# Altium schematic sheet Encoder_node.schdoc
size 594 x 419 mm; Symbol: Sheet-Symbol_A2; Company: 嘉立创EDA; Version: V1.0; Page Size: A2; @Project Name: CC_ESP32main; @Page Count: 1; @Update Date: 2026-03-14; @Create Date: 2026-03-14; @Schematic Name: Schematic1; @Page No: 1; @Page Name: P1; Device: Sheet-Symbol_A2; Border: 1; Title Block Position: 3; Width: 2338; Height: 1652; Region Start: 1; X Region Count: 6; Y Region Count: 4; Blade Width: 10; @Board Name: Board1; @Update Time: 19:06:50; @Create Time: 16:49:24
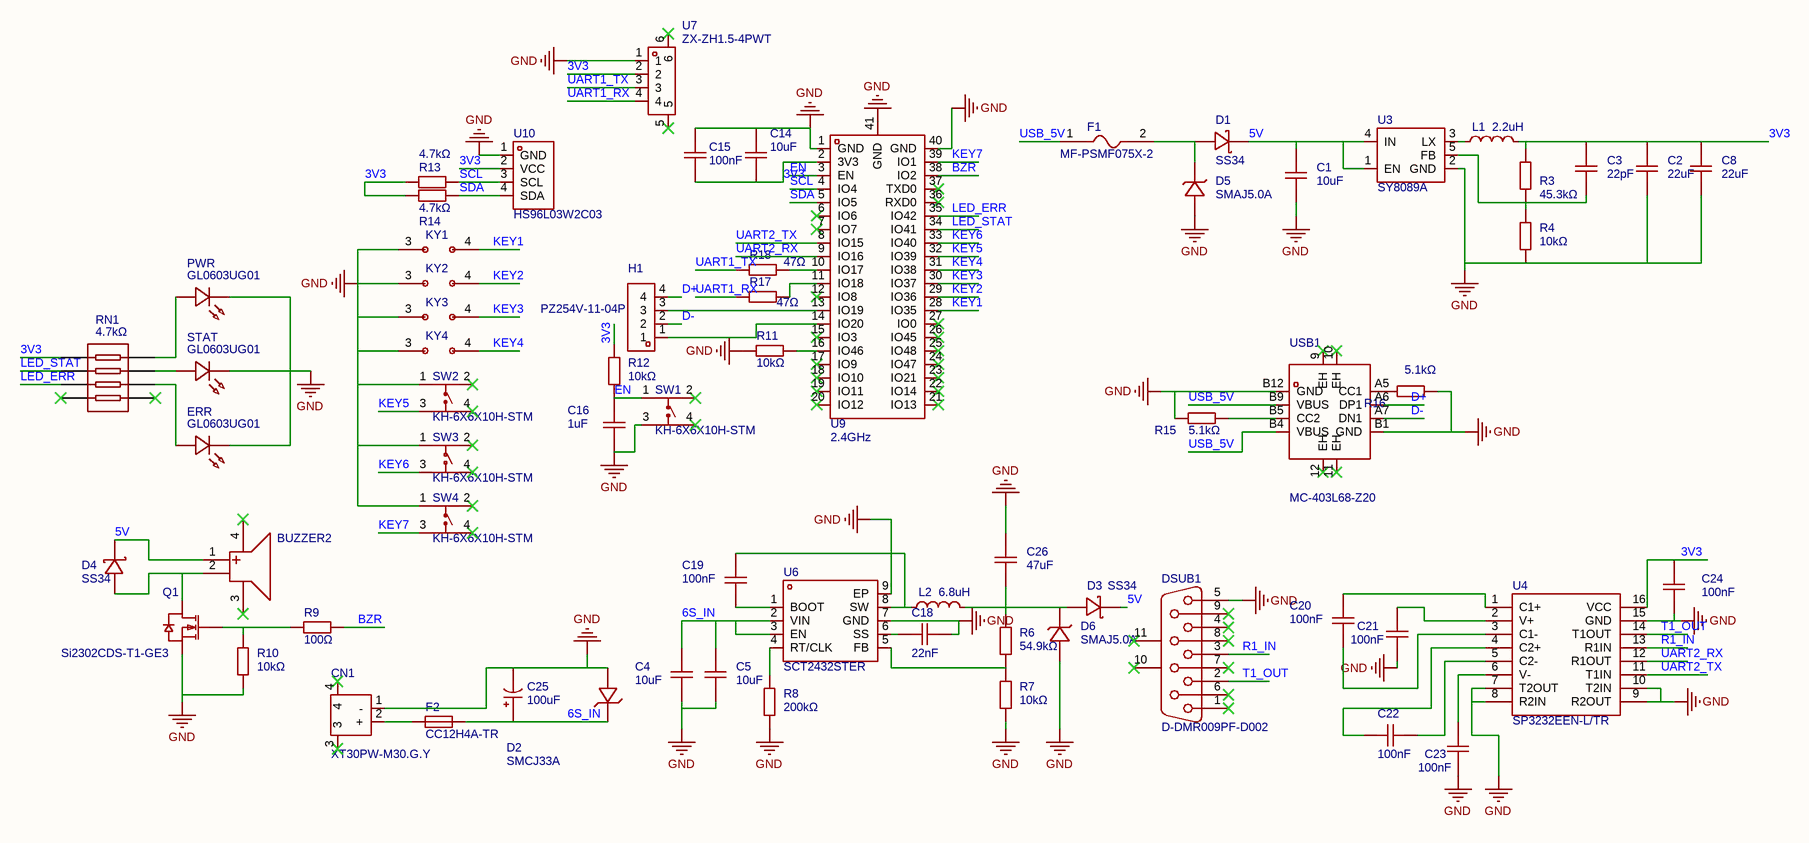
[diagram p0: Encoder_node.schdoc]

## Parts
BUZZER2  2.7kHz  [BUZ-SMD_GSC85XX]  (value not drawn)
C1  10uF  [C0603]
C2  22uF  [C0603]
C3  22pF  [C0603]
C4  10uF  [C1206]
C5  10uF  [C1206]
C8  22uF  [C0603]
C14  10uF  [C0603]
C15  100nF  [C0603]
C16  1uF  [C0603]
C18  22nF  [C0603]
C19  100nF  [C0603]
C20  100nF  [C0603]
C21  100nF  [C0603]
C22  100nF  [C0603]
C23  100nF  [C0603]
C24  100nF  [C0603]
C25  100uF  [CAP-SMD_BD6.3-L6.6-W6.6-LS7.3-FD-H7.7]
C26  47uF  [C1206]
CN1  XT30PW-M30.G.Y  [CONN-TH_XT30PW-M]
D1  SS34  [SMA_L4.3-W2.6-LS5.2-RD]
D2  SMCJ33A  [SMC_L6.9-W5.9-LS7.9-RD]
D3  SS34  [SMA_L4.3-W2.6-LS5.2-RD]
D4  SS34  [SMA_L4.3-W2.6-LS5.2-RD]
D5  SMAJ5.0A  [SMA_L4.3-W2.6-LS5.0-RD]
D6  SMAJ5.0A  [SMA_L4.3-W2.6-LS5.0-RD]
DSUB1  D-DMR009PF-D002  [DSUB-TH_DMR-9S]
ERR  GL0603UG01  [LED0603-RD]
F1  MF-PSMF075X-2  [F0805]
F2  CC12H4A-TR  [F1206]
H1  PZ254V-11-04P  [HDR-TH_4P-P2.54-V-M]
KY1  (no value)  [封装_凯华热插拔-5脚]
KY2  (no value)  [封装_凯华热插拔-5脚]
KY3  (no value)  [封装_凯华热插拔-5脚]
KY4  (no value)  [封装_凯华热插拔-5脚]
L1  2.2uH  [IND-SMD_L4.6-W4.1_MHCI04015]
L2  6.8uH  [IND-SMD_L7.5-W6.6_SRG0650]
PWR  GL0603UG01  [LED0603-RD]
Q1  Si2302CDS-T1-GE3  [SOT-23_L2.9-W1.3-P1.90-LS2.4-BR]
R3  45.3kΩ  [R0603]
R4  10kΩ  [R0603]
R6  54.9kΩ  [R0603]
R7  10kΩ  [R0603]
R8  200kΩ  [R0603]
R9  100Ω  [R0603]
R10  10kΩ  [R0603]
R11  10kΩ  [R0603]
R12  10kΩ  [R0603]
R13  4.7kΩ  [R0603]
R14  4.7kΩ  [R0603]
R15  5.1kΩ  [R0603]
R16  5.1kΩ  [R0603]
R17  47Ω  [R0603]
R18  47Ω  [R0603]
RN1  4.7kΩ  [RES-ARRAY-SMD_0603-8P-L3.2-W1.6-BL]
STAT  GL0603UG01  [LED0603-RD]
SW1  KH-6X6X10H-STM  [SW-SMD_4P-L6.0-W6.0-P4.50-LS9.0-H10.0]
SW2  KH-6X6X10H-STM  [SW-SMD_4P-L6.0-W6.0-P4.50-LS9.0-H10.0]
SW3  KH-6X6X10H-STM  [SW-SMD_4P-L6.0-W6.0-P4.50-LS9.0-H10.0]
SW4  KH-6X6X10H-STM  [SW-SMD_4P-L6.0-W6.0-P4.50-LS9.0-H10.0]
U3  SY8089A  [SOT-23-5_L3.0-W1.7-P0.95-LS2.8-BL]
U4  SP3232EEN-L/TR  [SOIC-16_L9.9-W3.9-P1.27-LS6.0-BL]
U6  SCT2432STER  [ESOP-8_L4.9-W3.9-P1.27-LS6.0-BL-EP]
U7  ZX-ZH1.5-4PWT  [CONN-SMD_4P-P1.50_ZX-ZH1.5-4PWT]
U9  2.4GHz  [WIFIM-SMD_ESP32-S3-WROOM-1-N8]
U10  HS96L03W2C03  [OLED-TH_L27.8-W27.2-P2.54_C9900033791]
USB1  MC-403L68-Z20  [USB-C-SMD_MC-403L68-Z20]

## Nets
GND: C1.1 C2.1 C4.2 C5.2 C8.1 C14.2 C15.2 C16.1 C18.1 C21.2 C23.1 C24.1 C25.2 C26.1 CN1.1(-) D2.2(A) D5.2(A) D6.2(A) DSUB1.5 ERR.1(K) KY1.3 KY2.3 KY3.3 KY4.3 PWR.1(K) Q1.2(S) R4.1 R7.1 R8.1 R10.2 R11.1 R15.1 R16.2 STAT.1(K) SW1.3(C) SW2.1(A) SW3.1(A) SW4.1(A) U3.2(GND) U4.7(T2OUT) U4.8(R2IN) U4.9(R2OUT) U4.10(T2IN) U4.15(GND) U6.7(GND) U6.9(EP) U7.1 U9.1(GND) U9.40(GND) U9.41(GND) U10.1(GND) USB1.B1(GND) USB1.B12(GND)
3V3: C2.2 C3.2 C8.2 C14.1 C15.1 C24.2 L1.2 R3.2 R12.2 R13.1 R14.2 RN1.1 U4.16(VCC) U7.2 U9.2(3V3) U10.2(VCC)
5V: BUZZER2.1(+) C1.2 D1.1(K) D3.1(K) D4.1(K) U3.1(EN) U3.4(IN)
6S_IN: C4.1 C5.1 C25.1 D2.1(K) F2.2 U6.2(VIN) U6.3(EN)
BZR: R9.1 U9.38(IO2)
D+: H1.4 USB1.A6(DP1)
D-: H1.2 USB1.A7(DN1)
EN: C16.2 R12.1 SW1.1(A) U9.3(EN)
KEY1: KY1.4 U9.28(IO35)
KEY2: KY2.4 U9.29(IO36)
KEY3: KY3.4 U9.30(IO37)
KEY4: KY4.4 U9.31(IO38)
KEY5: SW2.3(C) U9.32(IO39)
KEY6: SW3.3(C) U9.33(IO40)
KEY7: SW4.3(C) U9.39(IO1)
LED_ERR: RN1.3 U9.35(IO42)
LED_STAT: RN1.2 U9.34(IO41)
R1_IN: DSUB1.3 U4.13(R1IN)
SCL: R13.2 U9.4(IO4) U10.3(SCL)
SDA: R14.1 U9.5(IO5) U10.4(SDA)
T1_OUT: DSUB1.2 U4.14(T1OUT)
UART1_RX: R17.1 U7.4
UART1_TX: R18.1 U7.3
UART2_RX: U4.12(R1OUT) U9.9(IO16)
UART2_TX: U4.11(T1IN) U9.8(IO15)
USB_5V: F1.1 USB1.B4(VBUS) USB1.B9(VBUS)
NetBUZZER2_2: BUZZER2.2(-) D4.2(A) Q1.3(D)
NetC3_1: C3.1 R3.1 R4.2 U3.5(FB)
NetC18_2: C18.2 U6.6(SS)
NetC19_1: C19.1 L2.1 U6.8(SW)
NetC19_2: C19.2 U6.1(BOOT)
NetC20_1: C20.1 U4.1(C1+)
NetC20_2: C20.2 U4.3(C1-)
NetC21_1: C21.1 U4.2(V+)
NetC22_1: C22.1 U4.4(C2+)
NetC22_2: C22.2 U4.5(C2-)
NetC23_2: C23.2 U4.6(V-)
NetC26_2: C26.2 D3.2(A) D6.1(K) L2.2 R6.2
NetCN1_2: CN1.2(+) F2.1
NetD1_2: D1.2(A) D5.1(K) F1.2
NetERR_2: ERR.2(A) RN1.6
NetH1_1: H1.1 U9.14(IO20)
NetH1_3: H1.3 U9.13(IO19)
NetL1_1: L1.1 U3.3(LX)
NetPWR_2: PWR.2(A) RN1.8
NetQ1_1: Q1.1(G) R9.2 R10.1
NetR6_1: R6.1 R7.2 U6.5(FB)
NetR8_2: R8.2 U6.4(RT/CLK)
NetR11_2: R11.2 U9.16(IO46)
NetR15_2: R15.2 USB1.B5(CC2)
NetR16_1: R16.1 USB1.A5(CC1)
NetR17_2: R17.2 U9.11(IO18)
NetR18_2: R18.2 U9.10(IO17)
NetRN1_7: RN1.7 STAT.2(A)

Not connected (* = marked no-connect by the designer): BUZZER2 3* 4*; CN1 3* 4*; DSUB1 1* 4* 6* 7* 8* 9* 10(MH1)* 11(MH2)*; RN1 4* 5*; SW1 2(B)* 4(D)*; SW2 2(B)* 4(D)*; SW3 2(B)* 4(D)*; SW4 2(B)* 4(D)*; U7 5* 6*; U9 6(IO6)* 7(IO7)* 12(IO8)* 15(IO3)* 17(IO9)* 18(IO10)* 19(IO11)* 20(IO12)* 21(IO13)* 22(IO14)* 23(IO21)* 24(IO47)* 25(IO48)* 26(IO45)* 27(IO0)* 36(RXD0)* 37(TXD0)*; USB1 9(EH)* 10(EH)* 11(EH)* 12(EH)*

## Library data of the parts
BUZZER2 = GSC8530YA-16R2700: 驱动方式:无源(外部驱动);构造类型:电磁式;频率:2.7kHz;声压(SPL):85dB;; Manufacturer: INGHAi(赢海); AddInBom: yes; ModelId: 336000c5a3324556be9726b4453771b80819f05c4eef4c71ace90d822a990e87; ModelName: BUZ-SMD_4P-L8.5-W8.5-H3.0; ModelTransform: 342.519,342.519,0,270,0,0,0,0,0; Voltage - Supply: 2V~4.5V; Sound Pressure Level(SPL): 85dB
C1-C3 C8 = CGA0603X5R106K100JT: 容值:10uF;精度:±10%;额定电压:10V;温度系数:X5R;; Manufacturer: HRE(芯声); AddInBom: yes; ModelId: ac125912035d415993ca9572d50418b10819f05c4eef4c71ace90d822a990e87; ModelName: C0603_L1.6-W0.8-H0.8; ModelTransform: 62.992,31.496,0,0,0,0,0,0,0; Tolerance: ±10%; Voltage Rating: 10V; Temperature Coefficient: X5R
C4 C5 = HGC1206R5106K500NSPJ: 容值:10uF;精度:±10%;额定电压:50V;温度系数:X5R;; Manufacturer: Chinocera(华瓷); AddInBom: yes; ModelId: e4be705b945545a48e666415e3682bd80819f05c4eef4c71ace90d822a990e87; ModelName: C1206_L3.2-W1.6-H1.3; ModelTransform: 125.984,62.992,0,0,0,0,0,0,0; Tolerance: ±10%; Voltage Rating: 50V; Temperature Coefficient: X5R
C14-C16 C18-C24 = CGA0603X5R106K100JT: 容值:10uF;精度:±10%;额定电压:10V;温度系数:X5R;; Manufacturer: HRE(芯声); 3D Model: ac125912035d415993ca9572d50418b10819f05c4eef4c71ace90d822a990e87; 3D Model Transform: 62.992,31.496,0,0,0,0,0,0,0; Tolerance: ±10%; Voltage Rating: 10V; Temperature Coefficient: X5R; AddInBom: yes; ModelName: C0603_L1.6-W0.8-H0.8
C25 = JVJ50V100M6x8: 容值:100uF;精度:±20%;额定电压:50V;纹波电流:140mA@120Hz;; Manufacturer: JIERR(捷而瑞); AddInBom: yes; ModelId: ccbda52dceed4b139172c40f75c9da3f0819f05c4eef4c71ace90d822a990e87; ModelTransform: 287.401,259.842,0,0,0,0,0,0,0; Tolerance: ±20%; Voltage Rating: 50V; Lifetime: 2000hrs@105℃
C26 = HGC1206R5106K500NSPJ: 容值:10uF;精度:±10%;额定电压:50V;温度系数:X5R;; Manufacturer: Chinocera(华瓷); 3D Model: e4be705b945545a48e666415e3682bd80819f05c4eef4c71ace90d822a990e87; 3D Model Transform: 125.984,62.992,0,0,0,0,0,0,0; Tolerance: ±10%; Voltage Rating: 50V; Temperature Coefficient: X5R; AddInBom: yes; ModelName: C1206_L3.2-W1.6-H1.3
CN1 = XT30PW-M30.G.Y: Socket,DCsupply,XT30,male,PIN:2; Manufacturer: AMASS(艾迈斯); AddInBom: yes; ModelId: 722652c2597f41cd937322584dc4b29b0819f05c4eef4c71ace90d822a990e87; ModelTransform: 523.621,549.2115,0,0,0,0,-0.005,-39.568,-78.74; Rated current: 15A; Rated voltage: 500VDC; Connector type: 航模插头; Wire gauge: 16/18/20AWG; contact resistance: 1.2mΩ; interface form: 公头
D1 D3 = SS34_C8678: 二极管配置:独立式;正向压降(Vf):550mV@3A;直流反向耐压(Vr):40V;整流电流:3A;; Manufacturer: MDD(辰达半导体); AddInBom: yes; ModelId: e3551acb3c5a4975a5e9d36087fe1fa20819f05c4eef4c71ace90d822a990e87; ModelTransform: 185.039,102.362,0,0,0,0,0,0,0; Diode Configuration: 独立式; Voltage - DC Reverse(Vr): 40V; Current - Rectified: 3A; Reverse Leakage Current (Ir): 500uA@40V; Operating Junction Temperature Range: -55℃~+125℃
D2 = SMCJ33A_C224049: 极性:单向;反向截止电压(Vrwm):33V;钳位电压:53.3V;峰值脉冲电流(Ipp):28.2A@10/1000us;峰值脉冲功率(Ppp):1.5kW@10/1000us;击穿电压:40.6V;; Manufacturer: Littelfuse(美国力特); AddInBom: yes; ModelId: 181deed3e51b4528a83dd624c23bafda0819f05c4eef4c71ace90d822a990e87; ModelTransform: 314.96,236.22,0,0,0,0,0,0,0; Polarity: 单向; Reverse Stand-Off Voltage (Vrwm): 33V; Clamping Voltage: 53.3V; Voltage - Breakdown: 40.6V; Reverse Leakage Current (Ir): 1uA; level of protection: IEC 61000-4-4；IEC 61000-4-2; Type: TVS
D4 = SS34_C8678: 二极管配置:独立式;正向压降(Vf):550mV@3A;直流反向耐压(Vr):40V;整流电流:3A;; Manufacturer: MDD(辰达半导体); 3D Model: e3551acb3c5a4975a5e9d36087fe1fa20819f05c4eef4c71ace90d822a990e87; 3D Model Transform: 185.039,102.362,0,0,0,0,0,0,0; Diode Configuration: 独立式; Voltage - DC Reverse(Vr): 40V; Current - Rectified: 3A; Reverse Leakage Current (Ir): 500uA@40V; Operating Junction Temperature Range: -55℃~+125℃; AddInBom: yes
D5 D6 = SMAJ5.0A_C19077523: 极性:单向;反向截止电压(Vrwm):5V;钳位电压:9.2V;峰值脉冲电流(Ipp):43.5A@10/1000us;峰值脉冲功率(Ppp):400W@10/1000us;击穿电压:7V;; Manufacturer: R+O(宏嘉诚); AddInBom: yes; ModelId: 8d2dd2e50a3a4b27821fa63d469a8f110819f05c4eef4c71ace90d822a990e87; ModelTransform: 196.85,102.362,0,0,0,0,0,0,0; Polarity: 单向; Reverse Stand-Off Voltage (Vrwm): 5V; Clamping Voltage: 9.2V; Voltage - Breakdown: 7V; Reverse Leakage Current (Ir): 800uA; Number of Channels: 单路; level of protection: IEC 61000-4-2; Type: TVS
DSUB1 = D-DMR009PF-D002: 连接器类型:常规D-Sub;公母:母;总PIN位数:9P;安装方式:弯插;排数:2;额定电流-信号脚:3A;工作温度:-45℃~+85℃;; Manufacturer: Ckmtw(灿科盟); Symbol: DMR-9S; AddInBom: yes; ModelId: 45662a01dd4a43f09f16f1e1b95d76320819f05c4eef4c71ace90d822a990e87; ModelTransform: 1216.533,728.34496,0,90,0,0,256.102,0.118,-137.795; Gender: 母; Current Rating-Signal: 3A
ERR PWR STAT = GL0603UG01: Manufacturer: Guiguang light(桂光光电); Add into BOM: yes; 3D Model: 3c2caa1a3e7d4a5a87f46b87d898ef41; 3D Model Transform: v2:[39.37007874015748,0,0,0,39.37007874015748,0,0,0,39.37007874015748,0.001,-0.001,0]
F1 = MF-PSMF075X-2: 耐压(Vmax):6V;最大电流(Imax):-;保持电流(Ihold):-;跳闸电流(Itrip):-;; Manufacturer: BOURNS; AddInBom: yes; ModelId: 57e2aa106f9143e8b6ab832aebb31c780819f05c4eef4c71ace90d822a990e87; ModelName: F0805_L2.1-W1.4-H0.8; ModelTransform: 82.677,55.118,0,0,0,0,0.0005,0,0; Voltage - Max: 6V; Power Dissipation: 600mW; Resistance - Initial (Ri) (Min): 90mΩ; Resistance - Post Trip (R1) (Max): 350mΩ
F2 = CC12H4A-TR: 类型:贴片式保险丝;额定电流:4A;额定电压:63V;分断能力:50A;; Manufacturer: EATON(伊顿); AddInBom: yes; ModelId: f1628daad26847a79b887277a2bc85410819f05c4eef4c71ace90d822a990e87; ModelName: F1206_L3.2-W1.7-H0.6; ModelTransform: 125.984,66.929,0,0,0,0,0,0,0; Type: 贴片式保险丝; Current Rating: 4A; Voltage Rating (DC): 63V; Melting I2t: 3.2; Interrupt Rating: 50A
H1 = PZ254V-11-04P: 插针结构:1x4P;间距:2.54mm;行距:-;圆针/方针:方针;安装方式:直插;排数:单排;总PIN位数:4P;额定电流:3A;额定电压:250V;配合针长度:6mm;塑高:2.5mm;端接针长度:3mm;触头材质:-;工作温度:-40℃~+105℃;颜色:黑色;; Manufacturer: XFCN(兴飞); Symbol: PZ254V-11-04P_C2691448; AddInBom: yes; ModelId: 112f4d05e8d64e99ab9a333894bea4f90819f05c4eef4c71ace90d822a990e87; ModelName: HDR-TH_4P-P2.54-M-LI-1X4P; ModelTransform: 399.999,104.7242,0,0,0,0,0,0,-118.11; Pin Structure: 1x4P; Pitch: 2.54mm; Circluar Pins/Square Pins: 方针; Current Rating: 3A; Voltage Rating (Max): 250V
KY1-KY4 = 凯华热插拔-5脚: AddInBom: yes
L1 = SRG0420-2R2-M: 电感值:2.2uH;精度:±20%;额定电流:4A;饱和电流(Isat):5A;类型:一体成型电感;; Manufacturer: JIERR(捷而瑞); AddInBom: yes; Tolerance: ±20%; Current Rating: 4A; Current - Saturation(Isat): 5A; DC Resistance(DCR): 49mΩ; Type: 一体成型电感
L2 = SRG0650-6R8-M: 电感值:6.8uH;精度:±20%;额定电流:6A;饱和电流(Isat):6.5A;类型:一体成型电感;; Manufacturer: JIERR(捷而瑞); AddInBom: yes; Tolerance: ±20%; Current Rating: 6A; Current - Saturation(Isat): 6.5A; DC Resistance(DCR): 32mΩ; Type: 一体成型电感
Q1 = Si2302CDS-T1-GE3: 类型:1个N沟道;漏源电压(Vdss):20V;连续漏极电流(Id):2.9A;导通电阻(RDS(on)@Vgs,Id):57mΩ@4.5V,3.6A;功率(Pd):550mW;阈值电压(Vgs(th)@Id):850mV@250uA;; Manufacturer: VISHAY(威世); 3D Model: c62791f0466c4ae2a892c056b845b0ca0819f05c4eef4c71ace90d822a990e87; 3D Model Transform: 98.64468,114.173,0,180,0,0,0.001,-0.002,0; Type: 1个N沟道; Drain Source Voltage (Vdss): 20V; Continuous Drain Current (Id): 2.9A; Power Dissipation (Pd): 550mW; Total Gate Charge (Qg@Vgs): 3.5nC@4.5V; Input Capacitance (Ciss@Vds): 320pF@10V; Reverse Transfer Capacitance (Crss@Vds): 5pF@10V; AddInBom: yes; ModelName: SOT-23-3P_L2.9-W1.3-H1.0-LS2.4-P0.95
R3 R4 R6-R8 = 0603WAF5101T5E: 电阻类型:厚膜电阻;阻值:5.1kΩ;精度:±1%;功率:100mW;工作电压:75V;温度系数:±100ppm/℃;; Manufacturer: UNI-ROYAL(厚声); AddInBom: yes; ModelId: fc143cca1e79419f9cd78b61e9279f080819f05c4eef4c71ace90d822a990e87; ModelTransform: 31.8897,63.7794,0,90,0,0,0,0,0; Tolerance: ±1%; Power(Watts): 100mW; Voltage-Supply(Max): 75V
R9-R18 = 0603WAF5101T5E: 电阻类型:厚膜电阻;阻值:5.1kΩ;精度:±1%;功率:100mW;工作电压:75V;温度系数:±100ppm/℃;; Manufacturer: UNI-ROYAL(厚声); 3D Model: fc143cca1e79419f9cd78b61e9279f080819f05c4eef4c71ace90d822a990e87; 3D Model Transform: 31.8897,63.7794,0,90,0,0,0,0,0; Tolerance: ±1%; Power(Watts): 100mW; Voltage-Supply(Max): 75V; AddInBom: yes
RN1 = 4D03WGJ0472T5E: Manufacturer: UNI-ROYAL(厚声); Add into BOM: yes; 3D Model: 551b3dd0a237409fa823f51b33d3f6d1; 3D Model Transform: v2:[39.37007874015748,0,0,0,39.37007874015748,0,0,0,39.37007874015748,0,0,0]; ModelName: R0603-8P_L3.2-W1.6-H0.6
SW1-SW4 = KH-6X6X10H-STM: 电路结构:单刀单掷;按钮形状:圆形按钮;安装方式:立贴;开关长度:6mm;开关宽度:6mm;开关高度:10mm;带支架:不带支架;触点电流:50mA;额定电压:12V;工作寿命:8万次;; Manufacturer: kinghelm(金航标); AddInBom: yes; ModelId: abf5895ced9e4fddb18440718d3315620819f05c4eef4c71ace90d822a990e87; ModelTransform: 354.33,236.25937,0,0,0,0,0,0,0; Circuit: 单刀单掷; Actuator Style: 圆形按钮; Switch Height: 10mm; with Bracket: 不带支架; Contact Current: 50mA; Voltage Rating: 12V; Actuator/Cap Color: 黑色; Life: 8万次
U3 = SY8089A: 功能类型:降压型;工作电压:2.5V~5.5V;输出电压:-;输出电流:2A;输出类型:可调;; Manufacturer: TECH PUBLIC(台舟); AddInBom: yes; ModelId: 0a2a1b8f50944f73965918ad6e5fe1670819f05c4eef4c71ace90d822a990e87; ModelName: SOT-23-5_L2.9-W1.6-H1.1-LS2.8-P0.95; ModelTransform: 118.60433,114.173,0,90,0,0,0.0005,0.0005,0; Function: 降压型; Output Current: 2A; Frequency - Switching: 1MHz; Synchronous Rectifier: 否; Number of Outputs: 1; Topology: 降压式; Quiescent Current: 50uA; Switch tube (built-in/external): 内置; Output Type: 可调
U4 = SP3232EEN-L/TR: 类型:收发器;数据速率:235Kbps;; Manufacturer: MaxLinear(迈凌); AddInBom: yes; ModelId: c21ec766ec2643efb3352f8441994f4e0819f05c4eef4c71ace90d822a990e87; ModelName: SOIC-16_L9.9-W3.9-H1.8-LS6.0-P1.27; ModelTransform: 389.763,236.454,0,0,0,0,0,0,0; Number of Drivers: 2; Voltage - Supply: 3V~5.5V
U6 = SCT2432STER: 功能类型:降压型;输出类型:固定;工作电压:3.8V~40V;输出电压:800mV~40V;输出电流:3.5A;; Manufacturer: SCT(芯洲科技); AddInBom: yes; ModelId: d3e00daa36c445139c055a3b9efb85d20819f05c4eef4c71ace90d822a990e87; ModelName: ESOP-8_L4.9-W3.9-H1.6-LS6.0-P1.27; ModelTransform: 240.157,192.913,0,90,0,0,0,0,0; Function: 降压型; Output Type: 固定; Output Current: 3.5A; Switching Frequency: 300kHz~2.2MHz; Synchronous Rectification: 是; Number of Outputs: 1; Topology: 降压式; Quiescent Current (Iq): 25uA; Switch tube (built-in/external): 内置
U7 = ZX-ZH1.5-4PWT: 插针结构:1x4P;间距:1.5mm;安装方式:卧贴;参考系列:ZH;总PIN数:4P;排数:1;每排PIN数:4;行距:-;额定电流:1A;触头材质:黄铜;触头镀层:锡;工作温度:-25℃~+85℃;; Manufacturer: Megastar(兆星); AddInBom: yes; ModelId: e4d7e67cd57849bbb8ee8d6cc11c6e1d0819f05c4eef4c71ace90d822a990e87; ModelTransform: 354.7237,255.905,0,0,0,0,-0.002,-26.024,0; Pins Structure: 1x4P; Pitch: 1.5mm; Reference Series: ZH; Number of PINs Per Row: 4; Current Rating: 1A; Voltage Rating: 250V; Plastic Material: LCP; Supplementary Features: 辅助焊脚; Z-Height of the Board: 3.8mm; X-Length of Bottom Edge on Board (Spacing Line): 9mm; Y-Width of Bottom Edge on Board: 6mm
U9 = ESP32-S3-WROOM-1-N4: 核心芯片:ESP32-S3;频率:2.4GHz;天线形式:板载PCB天线;发射功率:20.5dBm;接收灵敏度:-103.5dBm;; Manufacturer: ESPRESSIF(乐鑫); AddInBom: yes; ModelId: 25d155705bef4668966be497221d84bf0819f05c4eef4c71ace90d822a990e87; ModelTransform: 708.66,1003.935,0,0,0,0,0,145.669,0; Wireless Standard: Bluetooth5.0; Interface Type: I2C；GPIO；UART；SPI；USB；I2S; Voltage - Supply: 3V~3.6V; Receive  Current: 95mA; Send  Current: 355mA
U10 = HS96L03W2C03: 核心芯片:SSD1315芯片;接口类型:I2C;尺寸(inch):0.96;像素分辨率:128x64;; Manufacturer: HS(汉昇); 3D Model: bb65183306db4ca69fb52250be49b00e0819f05c4eef4c71ace90d822a990e87; 3D Model Transform: 1070.864,1094.486,0,0,0,0,0,-498.424,0; Interface: I2C; Dot Pixels: 128x64; Type of Drive: 无源(PMOLED); Display Range: 21.744x10.864mm; Display Color: 白色; Voltage - Supply: 2.8V~3.3V; Luminance: 180cd/m2; AddInBom: yes
USB1 = MC-403L68-Z20: 连接器类型:Type-C;公母:母;安装方式:卧贴;触点数量:8P;端口数量:1;额定电流 - 电源:3A;工作温度:-25℃~+85℃;; Manufacturer: HANBO(汉博); Connector Type: Type-C; Gender: 母; Number of Contacts: 8P; Number of Ports: 1; Current Rating-Power: 3A; Voltage Rating: 5V; Connect-Disconnect Life: 1万次; AddInBom: yes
